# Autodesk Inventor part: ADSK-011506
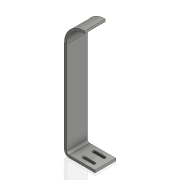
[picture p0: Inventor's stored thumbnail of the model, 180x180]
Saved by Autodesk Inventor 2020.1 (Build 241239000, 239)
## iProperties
Created: 2000-02
Part Number: ADSK-011506
Material: 1.0312 DC05
Description: FSHTPH,FS,CP,02,115,030,PLOW,END_TAB
Document SubType Name: Tôlerie
Designer: sspink
Density: 1 g/cm^3
Sheet Metal Rule: Stahlblech 1.0312 - DC05 -   6.0 mm
Appearance: Stahl
Mass: 114.383 g
Surface Area: 441.895 cm^2
Volume: 114.383 cm^3
Flat Pattern Width: 38.104 cm
Flat Pattern Length: 5.1 cm
Flat Pattern Area: 194.331 cm^2
Sheet Metal Width: 381,040 mm
Sheet Metal Length: 51,000 mm
Sheet Metal Area: 19433,064 mm^2
Control State: 0
Master: False
Checked Out: False
Shininess: 57.0
Length Units: 11269
Angle Units: 11279
Time Units: 11290
Mass Units: 11283
Length Display Precision: 3
Angle Display Precision: 2
Compacted: True
Cutlength: 15
Material Desc: FLAT,S/S,0.250 X 2.00
Material_number: A084860
G_L: 51x381 mm
Thickness: 6,000 mm
Dimensions: 76,2x291,7x51 mm
Mass: 0,114 kg
Semi finished: Stahlblech 1.0312 - DC05 -   6.0 mm
Density: 8.03
Volumn: 120.37339621202524
Area: 443.3774569794904
PropertySet Name: Model Information
Author: sspink
Revision Number: -
Title: FSHTPH,FS,CP,02,115,030,PLOW,END_TAB
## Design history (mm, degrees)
node "Solide1"
  node "Extrusion1" dims "d10" = 51, "d11" = 0
  node "Fillet3" dims "d14" = 12 (= 2 x thickness)
  node "Fillet4" dims "d15" = 6 (= thickness)
  node "Extrusion2" dims "d22" = 25.4, "d23" = 0
workplane "Arbeitsebene1"
workplane "Arbeitsebene2"
sketch "Sketch2"
  geometry: L1 (0, 51)-(0, 0) reference; L2 (-41, 9.5)-(-16, 9.5); L3 (-16, 9.5)-(-16, 16.5); L4 (-16, 16.5)-(-41, 16.5); L5 (-41, 16.5)-(-41, 9.5); L6 (-40.875, 34.5)-(-15.875, 34.5); L7 (-15.875, 34.5)-(-15.875, 41.5); L8 (-15.875, 41.5)-(-40.875, 41.5); L9 (-40.875, 41.5)-(-40.875, 34.5); L10 (-40.875, 38)-(-15.875, 38); L11 (-41, 13)-(-16, 13); L12 (-28.375, 38)-(-28.5, 13); A1 r 3.5 centre (-16, 13) between (-16, 9.5) and (-16, 16.5); A2 r 3.5 centre (-15.875, 38) between (-15.875, 34.5) and (-15.875, 41.5); A3 r 3.5 centre (-41, 13) between (-41, 16.5) and (-41, 9.5); A4 r 3.5 centre (-40.875, 38) between (-40.875, 41.5) and (-40.875, 34.5); 2 further points
  constraints: 22 end point, 8 point on circle, 6 parallel, 4 centre point, 4 horizontal, 4 midpoint, 4 tangent, 2 perpendicular, 1 horizontal alignment
  dimensions: "d16" = 7 distance between parallel lines of L4 L2; "d17" = 25 distance of L2.start L2.end; "d20" = 15.875 distance between parallel lines of L7 L1; "d21" = 16 distance between parallel lines of L3 L1; "d33" = 25 vertical distance of L12.start L12.end
node "FlatPattern"
node "Corps solides"
node "Corps surfaciques"
sketch "Sketch1"
  geometry: L1 (0, 0)-(1.465, 0); L2 (6, 6)-(6, 241.3); L3 (6, 241.3)-(0, 241.3); L4 (0, 241.3)-(0, 0); L5 (0, 0)-(76.2, 0); L6 (76.2, 0)-(76.2, 6); L7 (76.2, 6)-(6, 6); L8 (6, 241.3)-(50.45, 241.3); L9 (50.45, 241.3)-(50.45, 291.75); A1 r 44.45 centre (50.45, 241.3) between (50.45, 285.75) and (6, 241.3); A2 r 50.45 centre (50.45, 241.3) between (50.45, 291.75) and (0, 241.3)
  constraints: 18 end point, 4 parallel, 4 perpendicular, 4 point on circle, 2 centre point, 2 coincident, 1 horizontal, 1 point on line, 1 tangent
  dimensions: "d0" = 76.2 distance between parallel lines of L6 L4; "d1" = 241.3 distance between parallel lines of L3 L5; "d3" = 6 distance between parallel lines of L2 L4 (= thickness); "d4" = 6 distance between parallel lines of L7 L5 (= thickness); "d32" = 44.45 distance of L2.end L8.end
feature "Extrusion_mise_à_plat2" dims "d0" = 6 (derived)
other parameters: "thickness" = 6 [user parameter; used in 4 equation terms], "Thickness" = 6 (derived), "BendRadius" = 6 (= Thickness), "BendReliefWidth" = 6 (= Thickness), "BendReliefDepth" = 3 (= 0.5 x Thickness), "CornerReliefSize" = 24 (= 4 x Thickness), "SeamGap" = 0.00508, "MinimumRemnant" = 12 (= 2 x Thickness), "TransitionRadius" = 6 (= BendRadius), "TailleRayonJacobi" = 6 (= BendRadius), "TailleJeu" = 6 (= Thickness)
